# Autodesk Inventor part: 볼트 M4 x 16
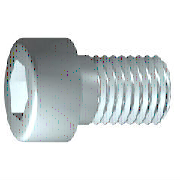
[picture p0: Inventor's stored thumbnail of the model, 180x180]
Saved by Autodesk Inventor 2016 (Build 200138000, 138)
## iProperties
IsCustomPart: 1
Created: 2012-02
Part Number: 볼트 M4 x 16
Material: 스테인리스강
Description: 6각 소켓 머리 캡 나사
Document SubType Name: Modeling
Standard: ISO 4762
Designer: mduedu
Standard Revision: Fourth edition 2004-03-01
Standards Organization: ISO
Language: ko-KR
Size Designation: M4 x 16
Categories: <MemberInstance><Categories><Category DisplayName="조임쇠" InternalName="e4da775c-781d-43d5-af7c-5136215cf5a6" Mnemonic="FSTN"><Category DisplayName="볼트" InternalN
Density: 8.08 g/cm^3
Appearance: 반광택
Author: mduedu
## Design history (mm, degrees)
sketch "스케치1"
  geometry: L1 (-1, 0)-(16, 0); L2 (16, 0)-(16, 2); L3 (16, 2)-(1.75, 2); L4 (1.75, 2)-(1.32, 2); L5 (1.32, 2)-(0, 2); L6 (0, 2)-(0, 3.5); L7 (0, 3.5)-(-4, 3.5); L8 (-4, 3.5)-(-4, 1.732); L9 (-4, 1.732)-(-2, 1.732); L10 (-2, 1.732)-(-1, 0); L11 (-8, 0)-(20, 0) reference; L12 (0, -0.7)-(0, 4.2) reference; L13 (1.75, 2)-(0, 2)
  constraints: 22 end point, 6 parallel, 2 collinear, 2 perpendicular, 1 horizontal, 1 point on line
  dimensions: "d1" = 14.25 distance from line of L3.end L2 (= GEL); "d2" = 0.42952 distance of L4.end L3.end (computed from GAL); "d3" = 4 distance between parallel lines of L8 L6 (= KOH); "d4" = 2 distance of L8.end L9.end (= INTI); "d5" = 60 deg angle of L10 L1; "d6" = 4 diameter of L3 L1 (= GD); "d7" = 4 diameter of L5 L1 (= BDM); "d8" = 3.4641 diameter of L9 L1 (= 1.1547 x SW); "d9" = 7 diameter of L7 L1 (= KOD); "d26" = 16 distance between parallel lines of L12 L2 (= NLG)
revolve "본체" sketch "스케치1" stored, may be unused: angle "d10" = 90 deg
sketch "스케치2"
  geometry: L1 (0, -4.9)-(0, 4.9) reference; L2 (-4.9, 0)-(4.9, 0) reference; L3 (1.732, 0)-(0.866, -1.5); L4 (0.866, -1.5)-(-0.866, -1.5); L5 (-0.866, -1.5)-(-1.732, 0); L6 (-1.732, 0)-(-0.866, 1.5); L7 (-0.866, 1.5)-(0.866, 1.5); L8 (0.866, 1.5)-(1.732, 0); 2 further points
  constraints: 12 end point, 1 coincident, 1 horizontal alignment, 1 point on line, 12 other
extrude "슬롯" join sketch "스케치2" stored distance "d11" = 10; taper "d12" = 0 deg
workplane "Work Plane1"
fillet "Fillet2" dims "d30" = 0.1 (= R)
body "Solid1"
fillet "모깎기1" dims "d17" = 0.4 (= RR)
feature "스레드" dims "d13" = 14.25 (= GEL), "d14" = 0
chamfer "모따기1" distance "d15" = 0.42941 (= -0.5 x SPD + 0.5 x GD); stored, may be unused: second distance "d16" = 0.42941 (= GUL), angle "d27" = 45 deg
other parameters: "GD" = 4 [user parameter; used in 2 equation terms], "NLG" = 16 [user parameter; used in 1 equation term], "GEL" = 14.25 [user parameter; used in 2 equation terms], "KOD" = 7 [user parameter; used in 1 equation term], "KOH" = 4 [user parameter; used in 1 equation term], "INTI" = 2 [user parameter; used in 1 equation term], "GAL" = 0.42941 (= 0.61345 x PTC) [user parameter; used in 1 equation term], "GUL" = 0.42941 (= 0.61345 x PTC) [user parameter; used in 1 equation term], "BDM" = 4 (= NND) [user parameter; used in 1 equation term], "SW" = 3 [user parameter; used in 2 equation terms], "RR" = 0.4 [user parameter; used in 1 equation term], "SPD" = 3.14117 (= NND - 1.2269 x PTC) [user parameter; used in 1 equation term], "d19" = 0, "d28" = 0, "d29" = 0, "R" = 0.1 [user parameter; used in 1 equation term], "TOA" = 30 deg [user parameter], "GD1" = 3.14117 (= THREADDIA - 1.2269 x PTC) [user parameter], "THREADDIA" = 4 [user parameter; used in 1 equation term], "FAWI" = 45 deg [user parameter], "TPU" = 14.28571 (computed from PTC) [user parameter], "PTC" = 0.7 [user parameter; used in 5 equation terms], "NND" = 4 [user parameter; used in 2 equation terms], "E0" = 3.465 (= 1.155 x SW) [user parameter]
